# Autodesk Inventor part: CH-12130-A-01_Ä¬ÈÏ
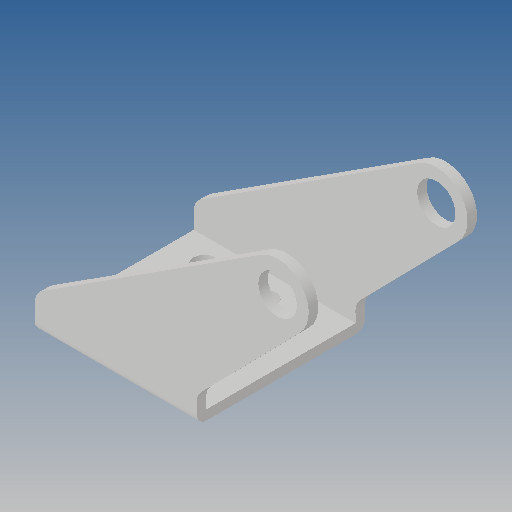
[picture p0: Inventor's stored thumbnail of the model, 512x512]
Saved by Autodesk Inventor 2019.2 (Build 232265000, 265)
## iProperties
Created: 2010-06
Part Number: CH-12130-A-01_Ä¬ÈÏ
Material: Ogólny
Document SubType Name: Modeling
Designer: CADENGINEERING4
Density: 1 g/cm^3
Appearance: Domyślna
Author: CADENGINEERING4
Revision Number: ÈÎºÎ
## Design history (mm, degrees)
feature "NONE"
node "Bryła1"
